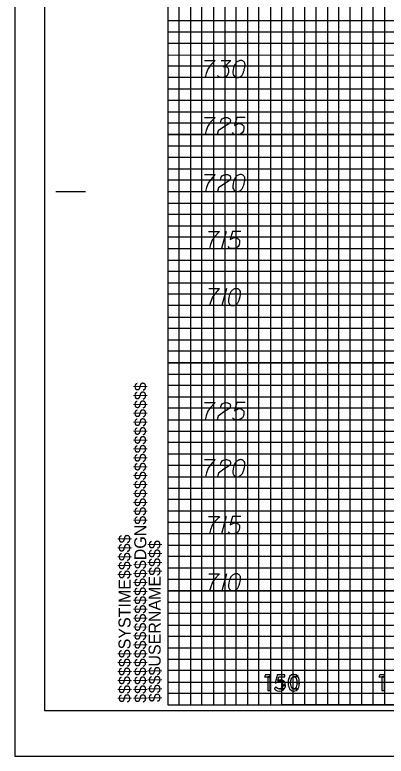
# Model space of a CAD drawing. Extents: x -13 to 323, y -5 to 1431.
# Drawn here: x -13.4 to 19.1, y 875.5 to 940.5 of the extents above; entities that cross this region are included whole.
import ezdxf

# ---------------------------------------------------------------- set-up
doc = ezdxf.new("R2010")
doc.units = 0
for name, color, linetype in [('Prop XS Elevation Labels', 7, 'Continuous'), ('Prop XS Offset Labels', 7, 'Continuous'), ('Sheet Cross Section CELL', 7, 'Continuous'), ('Sheet Cross Section Grid Major CELL', 7, 'Continuous'), ('Sheet Cross Section Grid Middle CELL', 7, 'Continuous'), ('Sheet Cross Section Grid Minor 1 CELL', 7, 'Continuous'), ('Sheet Cross Section Grid Minor 2 CELL', 7, 'Continuous'), ('Sheet Cutting Line CELL', 7, 'Continuous'), ('Sheet DOT Grid CELL', 7, 'Continuous'), ('Sheet Plot Border Inside CELL', 7, 'Continuous'), ('Sheet Plot Border Outside CELL', 7, 'Continuous')]:
    doc.layers.add(name, color=color, linetype=linetype)

msp = doc.modelspace()

# ---------------------------------------------------------------- linework, layer by layer
at = {"layer": 'Prop XS Elevation Labels'}
for p, q in [((5.124, 921.5), (4.723, 920)), ((5.142, 916.5), (4.74, 915)), ((5.124, 896.5), (4.723, 895)), ((5.142, 891.5), (4.74, 890))]:
    msp.add_line(p, q, dxfattribs=at)
for points in [[(3.217, 936.5), (4.161, 936.5), (4.103, 936.441), (3.76, 936.075), (3.524, 935.744), (3.382, 935.354), (3.288, 935)], [(4.693, 936.5), (5.52, 936.5), (5.13, 936.098), (4.87, 935.969), (5.083, 935.969), (5.13, 935.957), (5.154, 935.945), (5.177, 935.933), (5.201, 935.921), (5.248, 935.886), (5.272, 935.85), (5.295, 935.815), (5.307, 935.779), (5.331, 935.697), (5.343, 935.626), (5.343, 935.591), (5.343, 935.543), (5.331, 935.472), (5.319, 935.425), (5.307, 935.378), (5.295, 935.342), (5.284, 935.319), (5.272, 935.295), (5.26, 935.272), (5.236, 935.236), (5.201, 935.189), (5.166, 935.154), (5.142, 935.13), (5.106, 935.106), (5.071, 935.083), (5.024, 935.059), (5, 935.047), (4.918, 935.024), (4.847, 935.012), (4.799, 935), (4.717, 935), (4.622, 935.012), (4.587, 935.024), (4.551, 935.035), (4.516, 935.047), (4.48, 935.071), (4.445, 935.094), (4.386, 935.142), (4.351, 935.189)], [(6.429, 936.5), (6.405, 936.5), (6.334, 936.488), (6.287, 936.476), (6.252, 936.465), (6.193, 936.441), (6.122, 936.406), (6.063, 936.37), (6.004, 936.323), (5.968, 936.276), (5.933, 936.217), (5.897, 936.158), (5.862, 936.087), (5.838, 936.039), (5.815, 935.969), (5.779, 935.85), (5.744, 935.673), (5.72, 935.531), (5.72, 935.402), (5.732, 935.307), (5.779, 935.201), (5.815, 935.142), (5.874, 935.071), (5.945, 935.024), (5.98, 935.012), (6.051, 935), (6.11, 935), (6.204, 935.012), (6.287, 935.035), (6.346, 935.071), (6.429, 935.13), (6.464, 935.165), (6.512, 935.213), (6.547, 935.26), (6.571, 935.295), (6.594, 935.354), (6.606, 935.378), (6.63, 935.437), (6.653, 935.508), (6.677, 935.579), (6.689, 935.626), (6.7, 935.661), (6.712, 935.709), (6.736, 935.815), (6.748, 935.874), (6.76, 935.933), (6.771, 936.016), (6.783, 936.122), (6.783, 936.158), (6.771, 936.205), (6.76, 936.252), (6.724, 936.323), (6.689, 936.37), (6.653, 936.406), (6.606, 936.441), (6.559, 936.465), (6.523, 936.476), (6.488, 936.488), (6.429, 936.5)], [(3.211, 931.5), (4.155, 931.5), (4.096, 931.441), (3.754, 931.075), (3.518, 930.744), (3.376, 930.354), (3.281, 930)], [(4.616, 931.028), (4.675, 931.252), (4.77, 931.394), (4.876, 931.453), (4.982, 931.488), (5.065, 931.5), (5.124, 931.5), (5.23, 931.488), (5.301, 931.465), (5.337, 931.453), (5.408, 931.417), (5.443, 931.37), (5.467, 931.323), (5.478, 931.287), (5.49, 931.24), (5.49, 931.181), (5.478, 931.122), (5.467, 931.087), (5.443, 931.039), (5.408, 930.992), (5.372, 930.957), (4.888, 930.661), (4.427, 930.319), (4.345, 930), (5.419, 930)], [(6.789, 931.5), (6.045, 931.5), (5.856, 930.791), (6.199, 930.969), (6.4, 930.969), (6.565, 930.862), (6.66, 930.744), (6.683, 930.543), (6.648, 930.342), (6.553, 930.177), (6.388, 930.047), (6.104, 930), (5.892, 930), (5.785, 930.047), (5.691, 930.177)], [(3.228, 926.5), (4.173, 926.5), (4.114, 926.441), (3.772, 926.075), (3.535, 925.744), (3.394, 925.354), (3.299, 925)], [(4.634, 926.028), (4.693, 926.252), (4.787, 926.394), (4.894, 926.453), (5, 926.488), (5.083, 926.5), (5.142, 926.5), (5.248, 926.488), (5.319, 926.465), (5.354, 926.453), (5.425, 926.417), (5.461, 926.37), (5.484, 926.323), (5.496, 926.287), (5.508, 926.24), (5.508, 926.181), (5.496, 926.122), (5.484, 926.087), (5.461, 926.039), (5.425, 925.992), (5.39, 925.957), (4.906, 925.661), (4.445, 925.319), (4.362, 925), (5.437, 925)], [(6.417, 926.5), (6.394, 926.5), (6.323, 926.488), (6.276, 926.476), (6.24, 926.465), (6.181, 926.441), (6.11, 926.406), (6.051, 926.37), (5.992, 926.323), (5.957, 926.276), (5.921, 926.217), (5.886, 926.158), (5.85, 926.087), (5.827, 926.039), (5.803, 925.969), (5.768, 925.85), (5.732, 925.673), (5.709, 925.531), (5.709, 925.402), (5.721, 925.307), (5.768, 925.201), (5.803, 925.142), (5.862, 925.071), (5.933, 925.024), (5.968, 925.012), (6.039, 925), (6.098, 925), (6.193, 925.012), (6.276, 925.035), (6.335, 925.071), (6.417, 925.13), (6.453, 925.165), (6.5, 925.213), (6.535, 925.26), (6.559, 925.295), (6.583, 925.354), (6.594, 925.378), (6.618, 925.437), (6.642, 925.508), (6.665, 925.579), (6.677, 925.626), (6.689, 925.661), (6.701, 925.709), (6.724, 925.815), (6.736, 925.874), (6.748, 925.933), (6.76, 926.016), (6.772, 926.122), (6.772, 926.158), (6.76, 926.205), (6.748, 926.252), (6.713, 926.323), (6.677, 926.37), (6.642, 926.406), (6.594, 926.441), (6.547, 926.465), (6.512, 926.476), (6.476, 926.488), (6.417, 926.5)], [(3.589, 921.5), (4.533, 921.5), (4.474, 921.441), (4.132, 921.075), (3.896, 920.744), (3.754, 920.354), (3.659, 920)], [(6.411, 921.5), (5.667, 921.5), (5.478, 920.791), (5.821, 920.969), (6.022, 920.969), (6.187, 920.862), (6.282, 920.744), (6.305, 920.543), (6.27, 920.342), (6.175, 920.177), (6.01, 920.047), (5.726, 920), (5.514, 920), (5.408, 920.047), (5.313, 920.177)], [(3.606, 916.5), (4.551, 916.5), (4.492, 916.441), (4.149, 916.075), (3.913, 915.744), (3.772, 915.354), (3.677, 915)], [(6.039, 916.5), (6.016, 916.5), (5.945, 916.488), (5.898, 916.476), (5.862, 916.465), (5.803, 916.441), (5.732, 916.406), (5.673, 916.37), (5.614, 916.323), (5.579, 916.276), (5.543, 916.217), (5.508, 916.158), (5.472, 916.087), (5.449, 916.039), (5.425, 915.969), (5.39, 915.85), (5.354, 915.673), (5.331, 915.531), (5.331, 915.402), (5.343, 915.307), (5.39, 915.201), (5.425, 915.142), (5.484, 915.071), (5.555, 915.024), (5.591, 915.012), (5.661, 915), (5.72, 915), (5.815, 915.012), (5.898, 915.035), (5.957, 915.071), (6.039, 915.13), (6.075, 915.165), (6.122, 915.213), (6.157, 915.26), (6.181, 915.295), (6.205, 915.354), (6.217, 915.378), (6.24, 915.437), (6.264, 915.508), (6.287, 915.579), (6.299, 915.626), (6.311, 915.661), (6.323, 915.709), (6.347, 915.815), (6.358, 915.874), (6.37, 915.933), (6.382, 916.016), (6.394, 916.122), (6.394, 916.158), (6.382, 916.205), (6.37, 916.252), (6.335, 916.323), (6.299, 916.37), (6.264, 916.406), (6.217, 916.441), (6.169, 916.465), (6.134, 916.476), (6.098, 916.488), (6.039, 916.5)], [(3.211, 906.5), (4.155, 906.5), (4.096, 906.441), (3.754, 906.075), (3.518, 905.744), (3.376, 905.354), (3.281, 905)], [(4.616, 906.028), (4.675, 906.252), (4.77, 906.394), (4.876, 906.453), (4.982, 906.488), (5.065, 906.5), (5.124, 906.5), (5.23, 906.488), (5.301, 906.465), (5.337, 906.453), (5.408, 906.417), (5.443, 906.37), (5.467, 906.323), (5.478, 906.287), (5.49, 906.24), (5.49, 906.181), (5.478, 906.122), (5.467, 906.087), (5.443, 906.039), (5.408, 905.992), (5.372, 905.957), (4.888, 905.661), (4.427, 905.319), (4.345, 905), (5.419, 905)], [(6.789, 906.5), (6.045, 906.5), (5.856, 905.791), (6.199, 905.969), (6.4, 905.969), (6.565, 905.862), (6.66, 905.744), (6.683, 905.543), (6.648, 905.342), (6.553, 905.177), (6.388, 905.047), (6.104, 905), (5.892, 905), (5.785, 905.047), (5.691, 905.177)], [(3.228, 901.5), (4.173, 901.5), (4.114, 901.441), (3.772, 901.075), (3.535, 900.744), (3.394, 900.354), (3.299, 900)], [(4.634, 901.028), (4.693, 901.252), (4.787, 901.394), (4.894, 901.453), (5, 901.488), (5.083, 901.5), (5.142, 901.5), (5.248, 901.488), (5.319, 901.465), (5.354, 901.453), (5.425, 901.417), (5.461, 901.37), (5.484, 901.323), (5.496, 901.287), (5.508, 901.24), (5.508, 901.181), (5.496, 901.122), (5.484, 901.087), (5.461, 901.039), (5.425, 900.992), (5.39, 900.957), (4.906, 900.661), (4.445, 900.319), (4.362, 900), (5.437, 900)], [(6.417, 901.5), (6.394, 901.5), (6.323, 901.488), (6.276, 901.476), (6.24, 901.465), (6.181, 901.441), (6.11, 901.406), (6.051, 901.37), (5.992, 901.323), (5.957, 901.276), (5.921, 901.217), (5.886, 901.158), (5.85, 901.087), (5.827, 901.039), (5.803, 900.969), (5.768, 900.85), (5.732, 900.673), (5.709, 900.531), (5.709, 900.402), (5.721, 900.307), (5.768, 900.201), (5.803, 900.142), (5.862, 900.071), (5.933, 900.024), (5.968, 900.012), (6.039, 900), (6.098, 900), (6.193, 900.012), (6.276, 900.035), (6.335, 900.071), (6.417, 900.13), (6.453, 900.165), (6.5, 900.213), (6.535, 900.26), (6.559, 900.295), (6.583, 900.354), (6.594, 900.378), (6.618, 900.437), (6.642, 900.508), (6.665, 900.579), (6.677, 900.626), (6.689, 900.661), (6.701, 900.709), (6.724, 900.815), (6.736, 900.874), (6.748, 900.933), (6.76, 901.016), (6.772, 901.122), (6.772, 901.158), (6.76, 901.205), (6.748, 901.252), (6.713, 901.323), (6.677, 901.37), (6.642, 901.406), (6.594, 901.441), (6.547, 901.465), (6.512, 901.476), (6.476, 901.488), (6.417, 901.5)], [(3.589, 896.5), (4.533, 896.5), (4.474, 896.441), (4.132, 896.075), (3.896, 895.744), (3.754, 895.354), (3.659, 895)], [(6.411, 896.5), (5.667, 896.5), (5.478, 895.791), (5.821, 895.969), (6.022, 895.969), (6.187, 895.862), (6.282, 895.744), (6.305, 895.543), (6.27, 895.342), (6.175, 895.177), (6.01, 895.047), (5.726, 895), (5.514, 895), (5.408, 895.047), (5.313, 895.177)], [(3.606, 891.5), (4.551, 891.5), (4.492, 891.441), (4.149, 891.075), (3.913, 890.744), (3.772, 890.354), (3.677, 890)], [(6.039, 891.5), (6.016, 891.5), (5.945, 891.488), (5.898, 891.476), (5.862, 891.465), (5.803, 891.441), (5.732, 891.406), (5.673, 891.37), (5.614, 891.323), (5.579, 891.276), (5.543, 891.217), (5.508, 891.158), (5.472, 891.087), (5.449, 891.039), (5.425, 890.969), (5.39, 890.85), (5.354, 890.673), (5.331, 890.531), (5.331, 890.402), (5.343, 890.307), (5.39, 890.201), (5.425, 890.142), (5.484, 890.071), (5.555, 890.024), (5.591, 890.012), (5.661, 890), (5.72, 890), (5.815, 890.012), (5.898, 890.035), (5.957, 890.071), (6.039, 890.13), (6.075, 890.165), (6.122, 890.213), (6.157, 890.26), (6.181, 890.295), (6.205, 890.354), (6.217, 890.378), (6.24, 890.437), (6.264, 890.508), (6.287, 890.579), (6.299, 890.626), (6.311, 890.661), (6.323, 890.709), (6.347, 890.815), (6.358, 890.874), (6.37, 890.933), (6.382, 891.016), (6.394, 891.122), (6.394, 891.158), (6.382, 891.205), (6.37, 891.252), (6.335, 891.323), (6.299, 891.37), (6.264, 891.406), (6.217, 891.441), (6.169, 891.465), (6.134, 891.476), (6.098, 891.488), (6.039, 891.5)]]:
    msp.add_lwpolyline(points, dxfattribs=at)
at = {"layer": 'Prop XS Offset Labels'}
for points in [[(8.581, 882.641), (8.492, 882.459), (8.99, 882.459), (8.99, 882.641)], [(8.781, 882.459), (8.781, 881.25), (8.99, 881.25), (8.99, 882.459)], [(9.427, 881.94), (9.424, 881.928), (9.495, 881.928), (9.508, 881.94), (9.524, 881.954), (9.595, 881.997), (9.627, 882.007), (9.697, 882.029), (9.811, 882.035), (10.219, 882.035), (10.211, 882.05), (10.076, 882.145), (9.655, 882.145), (9.658, 882.158), (9.658, 882.158), (9.663, 882.178), (9.738, 882.456), (10.263, 882.456), (10.263, 882.641), (9.6, 882.641), (9.554, 882.456), (9.486, 882.178), (9.481, 882.158), (9.478, 882.145), (9.454, 882.05), (9.451, 882.035), (9.449, 882.029), (9.444, 882.007), (9.441, 881.997), (9.431, 881.954)], [(9.692, 882.158), (9.655, 882.145), (10.076, 882.145), (10.058, 882.158), (9.961, 882.178), (9.75, 882.178)], [(9.888, 882.192), (9.75, 882.178), (9.96, 882.178), (9.888, 882.192)], [(10.851, 881.255), (11.051, 881.214), (11.245, 881.255), (11.256, 881.257), (11.422, 881.409), (11.047, 881.409), (11.038, 881.411), (11.033, 881.413), (10.928, 881.442), (10.841, 881.555), (10.841, 881.556), (10.841, 881.556), (10.813, 881.657), (10.813, 881.659), (10.793, 881.732), (10.792, 881.736), (10.774, 881.939), (10.774, 881.941), (10.774, 881.943), (10.792, 882.145), (10.812, 882.222), (10.813, 882.224), (10.839, 882.322), (10.84, 882.325), (10.928, 882.44), (11.041, 882.469), (11.045, 882.47), (11.055, 882.473), (11.425, 882.473), (11.262, 882.622), (11.254, 882.624), (11.053, 882.668), (11.053, 882.668), (10.845, 882.624), (10.843, 882.622), (10.681, 882.473), (10.678, 882.47), (10.678, 882.469), (10.665, 882.44), (10.618, 882.325), (10.617, 882.322), (10.577, 882.224), (10.576, 882.222), (10.568, 882.145), (10.547, 881.943), (10.547, 881.941), (10.547, 881.939), (10.567, 881.736), (10.568, 881.732), (10.575, 881.659), (10.575, 881.657), (10.616, 881.556), (10.617, 881.555), (10.663, 881.442), (10.675, 881.413), (10.676, 881.411), (10.679, 881.409), (10.848, 881.257)], [(11.312, 882.145), (11.328, 881.943), (11.555, 881.943), (11.536, 882.145), (11.528, 882.222), (11.527, 882.224), (11.527, 882.224), (11.488, 882.322), (11.488, 882.322), (11.487, 882.325), (11.441, 882.44), (11.44, 882.44), (11.429, 882.469), (11.428, 882.47), (11.425, 882.473), (11.055, 882.473), (11.065, 882.47), (11.068, 882.469), (11.175, 882.44), (11.262, 882.325), (11.265, 882.322), (11.291, 882.224), (11.291, 882.222)], [(18.581, 882.641), (18.492, 882.459), (18.99, 882.459), (18.99, 882.641)], [(18.781, 882.459), (18.781, 881.25), (18.99, 881.25), (18.99, 882.459)], [(9.626, 881.233), (9.762, 881.214), (9.959, 881.233), (9.968, 881.237), (10.091, 881.297), (10.091, 881.297), (10.141, 881.321), (10.185, 881.375), (10.204, 881.399), (9.793, 881.399), (9.683, 881.418), (9.682, 881.419), (9.679, 881.42), (9.596, 881.466), (9.586, 881.477), (9.58, 881.483), (9.58, 881.483), (9.529, 881.535), (9.497, 881.585), (9.497, 881.585), (9.451, 881.535), (9.404, 881.483), (9.399, 881.477), (9.39, 881.466), (9.348, 881.42), (9.347, 881.419), (9.348, 881.418), (9.363, 881.399), (9.382, 881.375), (9.445, 881.321), (9.474, 881.297), (9.598, 881.237)], [(9.424, 881.928), (9.482, 881.916), (9.495, 881.928)], [(9.9, 881.418), (9.793, 881.399), (10.204, 881.399), (10.22, 881.418), (10.221, 881.419), (10.222, 881.42), (10.222, 881.42), (10.259, 881.466), (10.268, 881.477), (10.27, 881.483), (10.284, 881.535), (10.299, 881.59), (10.322, 881.674), (10.318, 881.721), (10.105, 881.721), (10.097, 881.674), (10.082, 881.59), (10.047, 881.535), (10.014, 881.483), (10.004, 881.477), (9.987, 881.466), (9.913, 881.42), (9.905, 881.419)], [(10.083, 881.841), (10.105, 881.721), (10.318, 881.721), (10.307, 881.841), (10.307, 881.841), (10.303, 881.881), (10.284, 881.916), (10.278, 881.928), (10.271, 881.94), (10.263, 881.954), (10.24, 881.997), (10.235, 882.007), (10.223, 882.029), (10.219, 882.035), (9.811, 882.035), (9.838, 882.029), (9.928, 882.007), (9.943, 881.997), (10.003, 881.954), (10.024, 881.94), (10.031, 881.928), (10.038, 881.916), (10.059, 881.881)], [(11.058, 881.411), (11.047, 881.409), (11.422, 881.409), (11.425, 881.411), (11.426, 881.413), (11.438, 881.442), (11.485, 881.555), (11.485, 881.556), (11.527, 881.657), (11.528, 881.659), (11.535, 881.732), (11.535, 881.736), (11.555, 881.939), (11.556, 881.941), (11.555, 881.943), (11.328, 881.943), (11.328, 881.941), (11.328, 881.939), (11.312, 881.736), (11.312, 881.732), (11.292, 881.659), (11.291, 881.657), (11.264, 881.556), (11.263, 881.555), (11.175, 881.442), (11.063, 881.413)]]:
    msp.add_lwpolyline(points, close=True, dxfattribs=at)
at = {"layer": 'Sheet Cross Section CELL'}
for p, q in [((-9.8, 925), (-7.3, 925)), ((-9.7, 925), (-7.2, 925)), ((0, 880), (0, 880)), ((0, 880), (0, 880)), ((0, 880), (0, 880)), ((0, 880), (0, 880)), ((0, 880), (0, 880)), ((0, 880), (0, 880)), ((0, 880), (0, 880))]:
    msp.add_line(p, q, dxfattribs=at)
msp.add_lwpolyline([(320, 1090), (0, 1090), (0, 880), (320, 880)], close=True, dxfattribs=at)
at = {"layer": 'Sheet Cross Section Grid Major CELL'}
for p, q in [((10, 880), (10, 1090)), ((20, 880), (10, 880))]:
    msp.add_line(p, q, dxfattribs=at)
for points in [[(0, 940), (320, 940), (320, 930), (0, 930)], [(0, 920), (320, 920), (320, 910), (0, 910)], [(0, 900), (320, 900), (320, 890), (0, 890)]]:
    msp.add_lwpolyline(points, dxfattribs=at)
at = {"layer": 'Sheet Cross Section Grid Middle CELL'}
for points in [[(5, 1090), (5, 880), (15, 880), (15, 1090)], [(0, 925), (320, 925), (320, 935), (0, 935)], [(0, 905), (320, 905), (320, 915), (0, 915)], [(0, 885), (320, 885), (320, 895), (0, 895)]]:
    msp.add_lwpolyline(points, dxfattribs=at)
at = {"layer": 'Sheet Cross Section Grid Minor 1 CELL'}
for points in [[(0, 939), (320, 939), (320, 938), (0, 938)], [(0, 936.99), (320.07, 936.91), (320, 936), (0, 936)], [(0, 934), (320, 934), (320, 933), (0, 933)], [(0, 932), (320, 932), (320, 931), (0, 931)], [(0, 929), (320, 929), (320, 928), (0, 928)], [(0, 927), (320, 927), (320, 926), (0, 926)], [(0, 924), (320, 924), (320, 923), (0, 923)], [(0, 922), (320, 922), (320, 921), (0, 921)], [(0, 919), (320, 919), (320, 918), (0, 918)], [(0, 917), (320, 917), (320, 916), (0, 916)], [(0, 914), (320, 914), (320, 913), (0, 913)], [(0, 912), (320, 912), (320, 911), (0, 911)], [(0, 909), (320, 909), (320, 908), (0, 908)], [(0, 907), (320, 907), (320, 906), (0, 906)], [(0, 904), (320, 904), (320, 903), (0, 903)], [(0, 902), (320, 902), (320, 901), (0, 901)], [(0, 899), (320, 899), (320, 898), (0, 898)], [(0, 897), (320, 897), (320, 896), (0, 896)], [(0, 894), (320, 894), (320, 893), (0, 893)], [(0, 892), (320, 892), (320, 891), (0, 891)], [(0, 889), (320, 889), (320, 888), (0, 888)], [(0, 887), (320, 887), (320, 886), (0, 886)], [(0, 884), (320, 884), (320, 883), (0, 883)], [(0, 882), (320, 882), (320, 881), (0, 881)]]:
    msp.add_lwpolyline(points, dxfattribs=at)
at = {"layer": 'Sheet Cross Section Grid Minor 2 CELL'}
for points in [[(0, 880), (1, 880), (1, 1090), (2, 1090), (2, 880)], [(2, 880), (3, 880), (3, 1090), (4, 1090), (4, 880)], [(5, 880), (6, 880), (6, 1090), (7, 1090), (7, 880)], [(7, 880), (8, 880), (8, 1090), (9, 1090), (9, 880)], [(10, 880), (11, 880), (11, 1090), (12, 1090), (12, 880)], [(12, 880), (13, 880), (13, 1090), (14, 1090), (14, 880)], [(15, 880), (16, 880), (16, 1090), (17, 1090), (17, 880)], [(17, 880), (18, 880), (18, 1090), (19, 1090), (19, 880)]]:
    msp.add_lwpolyline(points, dxfattribs=at)
at = {"layer": 'Sheet Cutting Line CELL'}
for p, q in [((-13.4, 1094.5), (-13.4, 875.5)), ((-13.4, 875.5), (323.3, 875.5))]:
    msp.add_line(p, q, dxfattribs=at)
at = {"layer": 'Sheet DOT Grid CELL'}
for p, q in [((10, 880), (10, 1090)), ((0, 940), (320, 940)), ((0, 930), (320, 930)), ((0, 920), (320, 920)), ((0, 910), (320, 910)), ((0, 900), (320, 900)), ((0, 890), (320, 890))]:
    msp.add_line(p, q, dxfattribs=at)
at = {"layer": 'Sheet Plot Border Inside CELL'}
msp.add_lwpolyline([(-10.8, 879.5), (322.4, 879.5), (322.4, 1090.5), (-10.8, 1090.5)], close=True, dxfattribs=at)
at = {"layer": 'Sheet Plot Border Outside CELL'}
msp.add_lwpolyline([(-13.4, 875.5), (323.3, 875.5), (323.3, 1094.5), (-13.4, 1094.5)], close=True, dxfattribs=at)

# ---------------------------------------------------------------- texts
at = {"layer": 'Sheet Cross Section CELL'}
for s, p in [('$$$$$$$$$$$$$$$$DGN$$$$$$$$$$$$$$$$', (-1.88, 880.18)), ('$$$$$$SYSTIME$$$$$', (-3.26, 880.18)), ('$$$$USERNAME$$$$', (-0.62, 880.23))]:
    msp.add_text(s, height=1.05, rotation=90, dxfattribs=at).set_placement(p)

doc.saveas('drawing.dxf')
